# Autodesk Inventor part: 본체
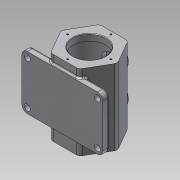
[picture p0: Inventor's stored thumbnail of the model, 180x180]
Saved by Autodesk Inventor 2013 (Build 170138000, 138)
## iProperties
Created: 2021-06
Part Number: 본체
Material: 알루미늄 6061
Document SubType Name: Modeling
Designer: Administrator
Mass: 1333.18 g
Surface Area: 1102.36 cm^2
Volume: 553.806 cm^3
Density: 2.40731 g/cm^3
Author: Administrator
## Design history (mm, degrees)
sketch "스케치1" dims "d0" = 105
  geometry: L1 (-52.5, 0)-(-26.25, 45.466); L2 (-26.25, 45.466)-(26.25, 45.466); L3 (26.25, 45.466)-(52.5, 0); L4 (52.5, 0)-(26.25, -45.466); L5 (26.25, -45.466)-(-26.25, -45.466); L6 (-26.25, -45.466)-(-52.5, 0); L7 (-73.5, 0)-(73.5, 0) reference; L8 (0, -73.5)-(0, 73.5) reference; 3 further points
  constraints: 12 end point, 2 coincident, 1 horizontal alignment, 15 other
  dimensions: "d2" = 30 deg angle of L8 L3
extrude "돌출1" new body sketch "스케치1" stored distance "d4" = 140; taper "d5" = 0 deg
sketch "스케치2"
  geometry: C1 r 30 at (0, 0); 1 further point
  constraints: 1 centre point, 1 coincident
  dimensions: "d6" = 60 diameter of C1
extrude "돌출2" cut sketch "스케치2" distance "d8" = 12; taper "d9" = 0 deg
sketch "스케치3"
  geometry: C1 r 30 at (0, 0) reference; C2 r 37.5 at (0, 0)
  constraints: 1 centre point, 1 coincident
  dimensions: "d10" = 75 diameter of C2
extrude "돌출3" cut sketch "스케치3" distance "d12" = 116; taper "d13" = 0 deg
sketch "스케치4"
  geometry: C1 r 30 at (0, 0); 1 further point
  constraints: 1 centre point, 1 coincident
  dimensions: "d14" = 60 diameter of C1
extrude "돌출4" cut sketch "스케치4" distance "d16" = 12; taper "d17" = 0 deg
node "작업 평면1"
sketch "스케치5"
  geometry: L1 (-26.25, 70)-(26.25, 70) reference; C1 r 20 at (0, 30); C2 r 20 at (0, -30); 1 further point
  constraints: 2 centre point, 2 vertical alignment
  dimensions: "d19" = 40 distance from line of L1 C1.centre; "d20" = 60 distance of C2.centre C1.centre; "d21" = 40 diameter of C1; "d22" = 40 diameter of C2
extrude "돌출5" join sketch "스케치5" stored distance "d23" = 8; taper "d24" = 0 deg
sketch "스케치6"
  geometry: C1 r 20 at (0, 0) reference; C2 r 20 at (0, 60) reference; C3 r 15 at (0, 0); C4 r 15 at (0, 60); 1 further point
  constraints: 2 centre point, 2 coincident
  dimensions: "d25" = 30 diameter of C3; "d27" = 30 diameter of C4
extrude "돌출6" cut sketch "스케치6" distance "d28" = 8; taper "d29" = 0 deg
sketch "스케치7"
  geometry: C1 r 15 at (0, 0) reference; C2 r 15 at (0, -60) reference; C3 r 12.5 at (0, 0); C4 r 12.5 at (0, -60); 1 further point
  constraints: 2 centre point, 2 coincident
  dimensions: "d30" = 25 diameter of C3; "d32" = 25 diameter of C4
extrude "돌출7" cut sketch "스케치7" distance "d33" = 20; taper "d34" = 0 deg
sketch "스케치8"
  geometry: C1 r 30 at (0, 0) reference; 1 further point
  constraints: 1 vertical alignment
  dimensions: "d35" = 40 distance of point (0, 40) C1.centre
hole "구멍1" sketch "스케치8" at (0, 40) diameter "d36" = 3.242; stored, may be unused: countersink angle "d40" = 90 deg, drill point angle "d42" = 118 deg; dims "d37" = 8, "d38" = 30, "d39" = 8, "d41" = 10
sketch "스케치9"
  geometry: L1 (0, 0)-(28.284, 28.284); L2 (73.5, 0)-(-73.5, 0) reference; C1 r 30 at (0, 0) reference; 1 further point
  constraints: 2 end point, 1 coincident
  dimensions: "d46" = 40 distance of L1.start L1.end; "d47" = 45 deg angle of L2 L1
hole "구멍2" sketch "스케치9" at (28.284, 28.284) diameter "d48" = 3.242; stored, may be unused: countersink angle "d52" = 90 deg, drill point angle "d54" = 118 deg; dims "d49" = 8, "d50" = 30, "d51" = 8, "d53" = 10
node "작업 평면2"
sketch "스케치10"
  geometry: L1 (-75, 55)-(75, 55); L2 (75, 55)-(75, -45); L3 (75, -45)-(-75, -45); L4 (-75, -45)-(-75, 55); L5 (128.2, 0)-(-139.2, 0) reference; L6 (0, -98)-(0, 98) reference; L7 (52.5, -70)-(26.25, -70) reference; 1 further point
  constraints: 8 end point, 2 parallel, 1 horizontal, 1 perpendicular, 1 other
  dimensions: "d59" = 150 distance between parallel lines of L4 L2; "d61" = 25 distance between parallel lines of L7 L3; "d62" = 100 distance between parallel lines of L3 L1
extrude "돌출8" join sketch "스케치10" distance "d63" = 12; taper "d64" = 0 deg
fillet "모깎기1" dims "d65" = 10
sketch "스케치11"
  geometry: C1 r 5.5 at (-65, 35); C2 r 5.5 at (-65, -45); C3 r 5.5 at (65, -45); C4 r 5.5 at (65, 35); A1 r 10 centre (-65, -45) between (-75, -45) and (-65, -55) reference; A2 r 10 centre (-65, 35) between (-65, 45) and (-75, 35) reference; A3 r 10 centre (65, 35) between (75, 35) and (65, 45) reference; A4 r 10 centre (65, -45) between (65, -55) and (75, -45) reference; 1 further point
  constraints: 4 centre point, 4 coincident
  dimensions: "d66" = 11 diameter of C1; "d68" = 11 diameter of C2; "d69" = 11 diameter of C3; "d70" = 11 diameter of C4
extrude "돌출9" cut sketch "스케치11" distance "d71" = 12; taper "d72" = 0 deg
sketch "스케치12"
  geometry: L1 (75, -45)-(75, 35) reference; L2 (30.561, -55)-(65, -55) reference; 2 further points
  constraints: 1 other
  dimensions: "d73" = 14 distance from line of L1 point (61, -5); "d74" = 50 distance from line of L2 point (61, -5)
feature "엠보싱1" sketch "스케치12" dims "d75" = 0.5, "d76" = 0
fillet "모깎기2" dims "d77" = 8
fillet "모깎기3" dims "d78" = 5
fillet "모깎기4" dims "d79" = 3
chamfer "모따기1" distance "d80" = 1; stored, may be unused: second distance "d81" = 2, angle "d82" = 45 deg
fillet "모깎기5" dims "d83" = 3
node "솔리드1"
pattern_circular "원형 패턴1" dims angle "d44" = 360 deg
pattern_circular "원형 패턴2" dims angle "d56" = 360 deg
other parameters: "d18" = 52.5
